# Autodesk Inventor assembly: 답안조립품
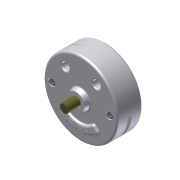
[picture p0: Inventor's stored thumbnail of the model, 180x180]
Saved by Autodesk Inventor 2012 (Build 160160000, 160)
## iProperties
Created: 2015-05
Part Number: 답안조립품
Document SubType Name: Assembly
Designer: ryu
Author: ryu
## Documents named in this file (10)
- J:\Inventor2급-권경란\답안조립품.iam
- J:\Inventor2급-권경란\본체.ipt
- J:\Inventor2급-권경란\덮개.ipt
- J:\Inventor2급-권경란\축.ipt
- J:\Inventor2급-권경란\슬라이더.ipt
- J:\Inventor2급-권경란\슬라이더2.ipt
- J:\Inventor2급-권경란\베어링62_22.ipt
- J:\Inventor2급-권경란\멈춤링.ipt
- J:\Inventor2급-권경란\평행핀.ipt
- J:\Inventor2급-권경란\M 10 x 35.ipt
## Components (2 placed, 1 different names)
1. M 10 x 35:1
2. M 10 x 35:2
